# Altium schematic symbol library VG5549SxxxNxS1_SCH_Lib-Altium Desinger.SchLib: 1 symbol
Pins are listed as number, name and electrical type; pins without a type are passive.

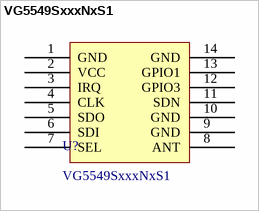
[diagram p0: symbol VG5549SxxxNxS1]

## VG5549SxxxNxS1
designator U?
footprint G55xxNS1
footprint G55xxNS1-TO
pins: 1 GND, 2 VCC, 3 IRQ, 4 CLK, 5 SDO, 6 SDI, 7 SEL, 8 ANT, 9 GND, 10 GND, 11 SDN, 12 GPIO3, 13 GPIO1, 14 GND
